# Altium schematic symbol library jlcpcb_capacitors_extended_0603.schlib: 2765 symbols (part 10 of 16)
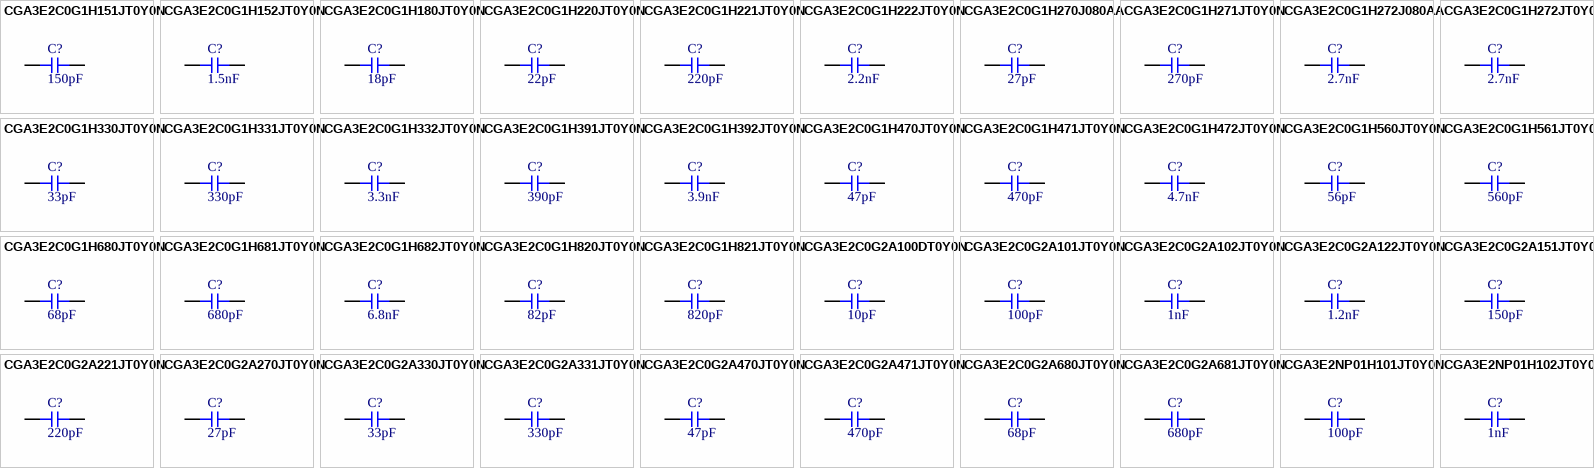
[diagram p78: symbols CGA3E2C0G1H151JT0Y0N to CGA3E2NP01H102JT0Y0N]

## CGA3E2C0G1H680JT0Y0N
designator C?  Capacitance: 68pF  (hidden comment: *)
Capacitor, Ceramic (MLCC), 68pF, ±5%, 50V, C0G, ±5%, SMD 0603; Manufacturer: TDK; Manufacturer Part Number: CGA3E2C0G1H680JT0Y0N
footprint CAP-0603 (0603 (1608M) Capacitor)
pins: 1, 2

## CGA3E2C0G1H681JT0Y0N
designator C?  Capacitance: 680pF  (hidden comment: *)
Capacitor, Ceramic (MLCC), 680pF, ±5%, 50V, C0G, ±5%, SMD 0603; Manufacturer: TDK; Manufacturer Part Number: CGA3E2C0G1H681JT0Y0N
footprint CAP-0603 (0603 (1608M) Capacitor)
pins: 1, 2

## CGA3E2C0G1H682JT0Y0N
designator C?  Capacitance: 6.8nF  (hidden comment: *)
Capacitor, Ceramic (MLCC), 6.8nF, ±5%, 50V, C0G, ±5%, SMD 0603; Manufacturer: TDK; Manufacturer Part Number: CGA3E2C0G1H682JT0Y0N
footprint CAP-0603 (0603 (1608M) Capacitor)
pins: 1, 2

## CGA3E2C0G1H820JT0Y0N
designator C?  Capacitance: 82pF  (hidden comment: *)
Capacitor, Ceramic (MLCC), 82pF, ±5%, 50V, C0G, ±5%, SMD 0603; Manufacturer: TDK; Manufacturer Part Number: CGA3E2C0G1H820JT0Y0N
footprint CAP-0603 (0603 (1608M) Capacitor)
pins: 1, 2

## CGA3E2C0G1H821JT0Y0N
designator C?  Capacitance: 820pF  (hidden comment: *)
Capacitor, Ceramic (MLCC), 820pF, ±5%, 50V, C0G, ±5%, SMD 0603; Manufacturer: TDK; Manufacturer Part Number: CGA3E2C0G1H821JT0Y0N
footprint CAP-0603 (0603 (1608M) Capacitor)
pins: 1, 2

## CGA3E2C0G2A100DT0Y0N
designator C?  Capacitance: 10pF  (hidden comment: *)
Capacitor, Ceramic (MLCC), 10pF, ±0.5pF, 100V, C0G, ±0.5pF, SMD 0603; Manufacturer: TDK; Manufacturer Part Number: CGA3E2C0G2A100DT0Y0N
footprint CAP-0603 (0603 (1608M) Capacitor)
pins: 1, 2

## CGA3E2C0G2A101JT0Y0N
designator C?  Capacitance: 100pF  (hidden comment: *)
Capacitor, Ceramic (MLCC), 100pF, ±5%, 100V, C0G, ±5%, SMD 0603; Manufacturer: TDK; Manufacturer Part Number: CGA3E2C0G2A101JT0Y0N
footprint CAP-0603 (0603 (1608M) Capacitor)
pins: 1, 2

## CGA3E2C0G2A102JT0Y0N
designator C?  Capacitance: 1nF  (hidden comment: *)
Capacitor, Ceramic (MLCC), 1nF, ±5%, 100V, C0G, ±5%, SMD 0603; Manufacturer: TDK; Manufacturer Part Number: CGA3E2C0G2A102JT0Y0N
footprint CAP-0603 (0603 (1608M) Capacitor)
pins: 1, 2

## CGA3E2C0G2A122JT0Y0N
designator C?  Capacitance: 1.2nF  (hidden comment: *)
Capacitor, Ceramic (MLCC), 1.2nF, ±5%, 100V, C0G, ±5%, SMD 0603; Manufacturer: TDK; Manufacturer Part Number: CGA3E2C0G2A122JT0Y0N
footprint CAP-0603 (0603 (1608M) Capacitor)
pins: 1, 2

## CGA3E2C0G2A151JT0Y0N
designator C?  Capacitance: 150pF  (hidden comment: *)
Capacitor, Ceramic (MLCC), 150pF, ±5%, 100V, C0G, ±5%, SMD 0603; Manufacturer: TDK; Manufacturer Part Number: CGA3E2C0G2A151JT0Y0N
footprint CAP-0603 (0603 (1608M) Capacitor)
pins: 1, 2

## CGA3E2C0G2A221JT0Y0N
designator C?  Capacitance: 220pF  (hidden comment: *)
Capacitor, Ceramic (MLCC), 220pF, ±5%, 100V, C0G, ±5%, SMD 0603; Manufacturer: TDK; Manufacturer Part Number: CGA3E2C0G2A221JT0Y0N
footprint CAP-0603 (0603 (1608M) Capacitor)
pins: 1, 2

## CGA3E2C0G2A270JT0Y0N
designator C?  Capacitance: 27pF  (hidden comment: *)
Capacitor, Ceramic (MLCC), 27pF, ±5%, 100V, C0G, ±5%, SMD 0603; Manufacturer: TDK; Manufacturer Part Number: CGA3E2C0G2A270JT0Y0N
footprint CAP-0603 (0603 (1608M) Capacitor)
pins: 1, 2

## CGA3E2C0G2A330JT0Y0N
designator C?  Capacitance: 33pF  (hidden comment: *)
Capacitor, Ceramic (MLCC), 33pF, ±5%, 100V, C0G, ±5%, SMD 0603; Manufacturer: TDK; Manufacturer Part Number: CGA3E2C0G2A330JT0Y0N
footprint CAP-0603 (0603 (1608M) Capacitor)
pins: 1, 2

## CGA3E2C0G2A331JT0Y0N
designator C?  Capacitance: 330pF  (hidden comment: *)
Capacitor, Ceramic (MLCC), 330pF, ±5%, 100V, C0G, ±5%, SMD 0603; Manufacturer: TDK; Manufacturer Part Number: CGA3E2C0G2A331JT0Y0N
footprint CAP-0603 (0603 (1608M) Capacitor)
pins: 1, 2

## CGA3E2C0G2A470JT0Y0N
designator C?  Capacitance: 47pF  (hidden comment: *)
Capacitor, Ceramic (MLCC), 47pF, ±5%, 100V, C0G, ±5%, SMD 0603; Manufacturer: TDK; Manufacturer Part Number: CGA3E2C0G2A470JT0Y0N
footprint CAP-0603 (0603 (1608M) Capacitor)
pins: 1, 2

## CGA3E2C0G2A471JT0Y0N
designator C?  Capacitance: 470pF  (hidden comment: *)
Capacitor, Ceramic (MLCC), 470pF, ±5%, 100V, C0G, ±5%, SMD 0603; Manufacturer: TDK; Manufacturer Part Number: CGA3E2C0G2A471JT0Y0N
footprint CAP-0603 (0603 (1608M) Capacitor)
pins: 1, 2

## CGA3E2C0G2A680JT0Y0N
designator C?  Capacitance: 68pF  (hidden comment: *)
Capacitor, Ceramic (MLCC), 68pF, ±5%, 100V, C0G, ±5%, SMD 0603; Manufacturer: TDK; Manufacturer Part Number: CGA3E2C0G2A680JT0Y0N
footprint CAP-0603 (0603 (1608M) Capacitor)
pins: 1, 2

## CGA3E2C0G2A681JT0Y0N
designator C?  Capacitance: 680pF  (hidden comment: *)
Capacitor, Ceramic (MLCC), 680pF, ±5%, 100V, C0G, ±5%, SMD 0603; Manufacturer: TDK; Manufacturer Part Number: CGA3E2C0G2A681JT0Y0N
footprint CAP-0603 (0603 (1608M) Capacitor)
pins: 1, 2

## CGA3E2NP01H101JT0Y0N
designator C?  Capacitance: 100pF  (hidden comment: *)
Capacitor, Ceramic (MLCC), 100pF, ±5%, 50V, NP0, ±5%, SMD 0603; Manufacturer: TDK; Manufacturer Part Number: CGA3E2NP01H101JT0Y0N
footprint CAP-0603 (0603 (1608M) Capacitor)
pins: 1, 2

## CGA3E2NP01H102JT0Y0N
designator C?  Capacitance: 1nF  (hidden comment: *)
Capacitor, Ceramic (MLCC), 1nF, ±5%, 50V, NP0, ±5%, SMD 0603; Manufacturer: TDK; Manufacturer Part Number: CGA3E2NP01H102JT0Y0N
footprint CAP-0603 (0603 (1608M) Capacitor)
pins: 1, 2

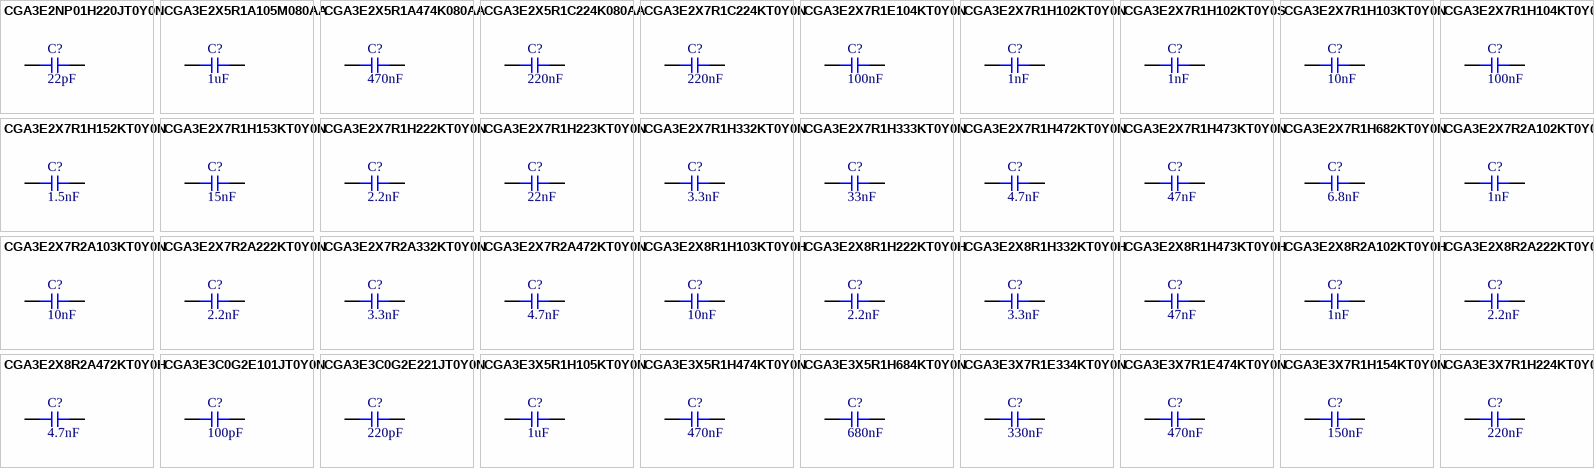
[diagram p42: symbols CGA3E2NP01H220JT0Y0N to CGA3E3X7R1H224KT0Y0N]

## CGA3E2NP01H220JT0Y0N
designator C?  Capacitance: 22pF  (hidden comment: *)
Capacitor, Ceramic (MLCC), 22pF, ±5%, 50V, NP0, ±5%, SMD 0603; Manufacturer: TDK; Manufacturer Part Number: CGA3E2NP01H220JT0Y0N
footprint CAP-0603 (0603 (1608M) Capacitor)
pins: 1, 2

## CGA3E2X5R1A105M080AA
designator C?  Capacitance: 1uF  (hidden comment: *)
Capacitor, Ceramic (MLCC), 1uF, ±20%, 10V, X5R, ±20%, SMD 0603; Manufacturer: TDK; Manufacturer Part Number: CGA3E2X5R1A105M080AA
footprint CAP-0603 (0603 (1608M) Capacitor)
pins: 1, 2

## CGA3E2X5R1A474K080AA
designator C?  Capacitance: 470nF  (hidden comment: *)
Capacitor, Ceramic (MLCC), 470nF, ±10%, 10V, X5R, ±10%, SMD 0603; Manufacturer: TDK; Manufacturer Part Number: CGA3E2X5R1A474K080AA
footprint CAP-0603 (0603 (1608M) Capacitor)
pins: 1, 2

## CGA3E2X5R1C224K080AA
designator C?  Capacitance: 220nF  (hidden comment: *)
Capacitor, Ceramic (MLCC), 220nF, ±10%, 16V, X5R, ±10%, SMD 0603; Manufacturer: TDK; Manufacturer Part Number: CGA3E2X5R1C224K080AA
footprint CAP-0603 (0603 (1608M) Capacitor)
pins: 1, 2

## CGA3E2X7R1C224KT0Y0N
designator C?  Capacitance: 220nF  (hidden comment: *)
Capacitor, Ceramic (MLCC), 220nF, ±10%, 16V, X7R, ±10%, SMD 0603; Manufacturer: TDK; Manufacturer Part Number: CGA3E2X7R1C224KT0Y0N
footprint CAP-0603 (0603 (1608M) Capacitor)
pins: 1, 2

## CGA3E2X7R1E104KT0Y0N
designator C?  Capacitance: 100nF  (hidden comment: *)
Capacitor, Ceramic (MLCC), 100nF, ±10%, 25V, X7R, ±10%, SMD 0603; Manufacturer: TDK; Manufacturer Part Number: CGA3E2X7R1E104KT0Y0N
footprint CAP-0603 (0603 (1608M) Capacitor)
pins: 1, 2

## CGA3E2X7R1H102KT0Y0N
designator C?  Capacitance: 1nF  (hidden comment: *)
Capacitor, Ceramic (MLCC), 1nF, ±10%, 50V, X7R, ±10%, SMD 0603; Manufacturer: TDK; Manufacturer Part Number: CGA3E2X7R1H102KT0Y0N
footprint CAP-0603 (0603 (1608M) Capacitor)
pins: 1, 2

## CGA3E2X7R1H102KT0Y0S
designator C?  Capacitance: 1nF  (hidden comment: *)
Capacitor, Ceramic (MLCC), 1nF, ±10%, 50V, X7R, ±10%, SMD 0603; Manufacturer: TDK; Manufacturer Part Number: CGA3E2X7R1H102KT0Y0S
footprint CAP-0603 (0603 (1608M) Capacitor)
pins: 1, 2

## CGA3E2X7R1H103KT0Y0N
designator C?  Capacitance: 10nF  (hidden comment: *)
Capacitor, Ceramic (MLCC), 10nF, ±10%, 50V, X7R, ±10%, SMD 0603; Manufacturer: TDK; Manufacturer Part Number: CGA3E2X7R1H103KT0Y0N
footprint CAP-0603 (0603 (1608M) Capacitor)
pins: 1, 2

## CGA3E2X7R1H104KT0Y0N
designator C?  Capacitance: 100nF  (hidden comment: *)
Capacitor, Ceramic (MLCC), 100nF, ±10%, 50V, X7R, ±10%, SMD 0603; Manufacturer: TDK; Manufacturer Part Number: CGA3E2X7R1H104KT0Y0N
footprint CAP-0603 (0603 (1608M) Capacitor)
pins: 1, 2

## CGA3E2X7R1H152KT0Y0N
designator C?  Capacitance: 1.5nF  (hidden comment: *)
Capacitor, Ceramic (MLCC), 1.5nF, ±10%, 50V, X7R, ±10%, SMD 0603; Manufacturer: TDK; Manufacturer Part Number: CGA3E2X7R1H152KT0Y0N
footprint CAP-0603 (0603 (1608M) Capacitor)
pins: 1, 2

## CGA3E2X7R1H153KT0Y0N
designator C?  Capacitance: 15nF  (hidden comment: *)
Capacitor, Ceramic (MLCC), 15nF, ±10%, 50V, X7R, ±10%, SMD 0603; Manufacturer: TDK; Manufacturer Part Number: CGA3E2X7R1H153KT0Y0N
footprint CAP-0603 (0603 (1608M) Capacitor)
pins: 1, 2

## CGA3E2X7R1H222KT0Y0N
designator C?  Capacitance: 2.2nF  (hidden comment: *)
Capacitor, Ceramic (MLCC), 2.2nF, ±10%, 50V, X7R, ±10%, SMD 0603; Manufacturer: TDK; Manufacturer Part Number: CGA3E2X7R1H222KT0Y0N
footprint CAP-0603 (0603 (1608M) Capacitor)
pins: 1, 2

## CGA3E2X7R1H223KT0Y0N
designator C?  Capacitance: 22nF  (hidden comment: *)
Capacitor, Ceramic (MLCC), 22nF, ±10%, 50V, X7R, ±10%, SMD 0603; Manufacturer: TDK; Manufacturer Part Number: CGA3E2X7R1H223KT0Y0N
footprint CAP-0603 (0603 (1608M) Capacitor)
pins: 1, 2

## CGA3E2X7R1H332KT0Y0N
designator C?  Capacitance: 3.3nF  (hidden comment: *)
Capacitor, Ceramic (MLCC), 3.3nF, ±10%, 50V, X7R, ±10%, SMD 0603; Manufacturer: TDK; Manufacturer Part Number: CGA3E2X7R1H332KT0Y0N
footprint CAP-0603 (0603 (1608M) Capacitor)
pins: 1, 2

## CGA3E2X7R1H333KT0Y0N
designator C?  Capacitance: 33nF  (hidden comment: *)
Capacitor, Ceramic (MLCC), 33nF, ±10%, 50V, X7R, ±10%, SMD 0603; Manufacturer: TDK; Manufacturer Part Number: CGA3E2X7R1H333KT0Y0N
footprint CAP-0603 (0603 (1608M) Capacitor)
pins: 1, 2

## CGA3E2X7R1H472KT0Y0N
designator C?  Capacitance: 4.7nF  (hidden comment: *)
Capacitor, Ceramic (MLCC), 4.7nF, ±10%, 50V, X7R, ±10%, SMD 0603; Manufacturer: TDK; Manufacturer Part Number: CGA3E2X7R1H472KT0Y0N
footprint CAP-0603 (0603 (1608M) Capacitor)
pins: 1, 2

## CGA3E2X7R1H473KT0Y0N
designator C?  Capacitance: 47nF  (hidden comment: *)
Capacitor, Ceramic (MLCC), 47nF, ±10%, 50V, X7R, ±10%, SMD 0603; Manufacturer: TDK; Manufacturer Part Number: CGA3E2X7R1H473KT0Y0N
footprint CAP-0603 (0603 (1608M) Capacitor)
pins: 1, 2

## CGA3E2X7R1H682KT0Y0N
designator C?  Capacitance: 6.8nF  (hidden comment: *)
Capacitor, Ceramic (MLCC), 6.8nF, ±10%, 50V, X7R, ±10%, SMD 0603; Manufacturer: TDK; Manufacturer Part Number: CGA3E2X7R1H682KT0Y0N
footprint CAP-0603 (0603 (1608M) Capacitor)
pins: 1, 2

## CGA3E2X7R2A102KT0Y0N
designator C?  Capacitance: 1nF  (hidden comment: *)
Capacitor, Ceramic (MLCC), 1nF, ±10%, 100V, X7R, ±10%, SMD 0603; Manufacturer: TDK; Manufacturer Part Number: CGA3E2X7R2A102KT0Y0N
footprint CAP-0603 (0603 (1608M) Capacitor)
pins: 1, 2

## CGA3E2X7R2A103KT0Y0N
designator C?  Capacitance: 10nF  (hidden comment: *)
Capacitor, Ceramic (MLCC), 10nF, ±10%, 100V, X7R, ±10%, SMD 0603; Manufacturer: TDK; Manufacturer Part Number: CGA3E2X7R2A103KT0Y0N
footprint CAP-0603 (0603 (1608M) Capacitor)
pins: 1, 2

## CGA3E2X7R2A222KT0Y0N
designator C?  Capacitance: 2.2nF  (hidden comment: *)
Capacitor, Ceramic (MLCC), 2.2nF, ±10%, 100V, X7R, ±10%, SMD 0603; Manufacturer: TDK; Manufacturer Part Number: CGA3E2X7R2A222KT0Y0N
footprint CAP-0603 (0603 (1608M) Capacitor)
pins: 1, 2

## CGA3E2X7R2A332KT0Y0N
designator C?  Capacitance: 3.3nF  (hidden comment: *)
Capacitor, Ceramic (MLCC), 3.3nF, ±10%, 100V, X7R, ±10%, SMD 0603; Manufacturer: TDK; Manufacturer Part Number: CGA3E2X7R2A332KT0Y0N
footprint CAP-0603 (0603 (1608M) Capacitor)
pins: 1, 2

## CGA3E2X7R2A472KT0Y0N
designator C?  Capacitance: 4.7nF  (hidden comment: *)
Capacitor, Ceramic (MLCC), 4.7nF, ±10%, 100V, X7R, ±10%, SMD 0603; Manufacturer: TDK; Manufacturer Part Number: CGA3E2X7R2A472KT0Y0N
footprint CAP-0603 (0603 (1608M) Capacitor)
pins: 1, 2

## CGA3E2X8R1H103KT0Y0H
designator C?  Capacitance: 10nF  (hidden comment: *)
Capacitor, Ceramic (MLCC), 10nF, ±10%, 50V, X8R, ±10%, SMD 0603; Manufacturer: TDK; Manufacturer Part Number: CGA3E2X8R1H103KT0Y0H
footprint CAP-0603 (0603 (1608M) Capacitor)
pins: 1, 2

## CGA3E2X8R1H222KT0Y0H
designator C?  Capacitance: 2.2nF  (hidden comment: *)
Capacitor, Ceramic (MLCC), 2.2nF, ±10%, 50V, X8R, ±10%, SMD 0603; Manufacturer: TDK; Manufacturer Part Number: CGA3E2X8R1H222KT0Y0H
footprint CAP-0603 (0603 (1608M) Capacitor)
pins: 1, 2

## CGA3E2X8R1H332KT0Y0H
designator C?  Capacitance: 3.3nF  (hidden comment: *)
Capacitor, Ceramic (MLCC), 3.3nF, ±10%, 50V, X8R, ±10%, SMD 0603; Manufacturer: TDK; Manufacturer Part Number: CGA3E2X8R1H332KT0Y0H
footprint CAP-0603 (0603 (1608M) Capacitor)
pins: 1, 2

## CGA3E2X8R1H473KT0Y0H
designator C?  Capacitance: 47nF  (hidden comment: *)
Capacitor, Ceramic (MLCC), 47nF, ±10%, 50V, X8R, ±10%, SMD 0603; Manufacturer: TDK; Manufacturer Part Number: CGA3E2X8R1H473KT0Y0H
footprint CAP-0603 (0603 (1608M) Capacitor)
pins: 1, 2

## CGA3E2X8R2A102KT0Y0H
designator C?  Capacitance: 1nF  (hidden comment: *)
Capacitor, Ceramic (MLCC), 1nF, ±10%, 100V, X8R, ±10%, SMD 0603; Manufacturer: TDK; Manufacturer Part Number: CGA3E2X8R2A102KT0Y0H
footprint CAP-0603 (0603 (1608M) Capacitor)
pins: 1, 2

## CGA3E2X8R2A222KT0Y0H
designator C?  Capacitance: 2.2nF  (hidden comment: *)
Capacitor, Ceramic (MLCC), 2.2nF, ±10%, 100V, X8R, ±10%, SMD 0603; Manufacturer: TDK; Manufacturer Part Number: CGA3E2X8R2A222KT0Y0H
footprint CAP-0603 (0603 (1608M) Capacitor)
pins: 1, 2

## CGA3E2X8R2A472KT0Y0H
designator C?  Capacitance: 4.7nF  (hidden comment: *)
Capacitor, Ceramic (MLCC), 4.7nF, ±10%, 100V, X8R, ±10%, SMD 0603; Manufacturer: TDK; Manufacturer Part Number: CGA3E2X8R2A472KT0Y0H
footprint CAP-0603 (0603 (1608M) Capacitor)
pins: 1, 2

## CGA3E3C0G2E101JT0Y0N
designator C?  Capacitance: 100pF  (hidden comment: *)
Capacitor, Ceramic (MLCC), 100pF, ±5%, 250V, C0G, ±5%, SMD 0603; Manufacturer: TDK; Manufacturer Part Number: CGA3E3C0G2E101JT0Y0N
footprint CAP-0603 (0603 (1608M) Capacitor)
pins: 1, 2

## CGA3E3C0G2E221JT0Y0N
designator C?  Capacitance: 220pF  (hidden comment: *)
Capacitor, Ceramic (MLCC), 220pF, ±5%, 250V, C0G, ±5%, SMD 0603; Manufacturer: TDK; Manufacturer Part Number: CGA3E3C0G2E221JT0Y0N
footprint CAP-0603 (0603 (1608M) Capacitor)
pins: 1, 2

## CGA3E3X5R1H105KT0Y0N
designator C?  Capacitance: 1uF  (hidden comment: *)
Capacitor, Ceramic (MLCC), 1uF, ±10%, 50V, X5R, ±10%, SMD 0603; Manufacturer: TDK; Manufacturer Part Number: CGA3E3X5R1H105KT0Y0N
footprint CAP-0603 (0603 (1608M) Capacitor)
pins: 1, 2

## CGA3E3X5R1H474KT0Y0N
designator C?  Capacitance: 470nF  (hidden comment: *)
Capacitor, Ceramic (MLCC), 470nF, ±10%, 50V, X5R, ±10%, SMD 0603; Manufacturer: TDK; Manufacturer Part Number: CGA3E3X5R1H474KT0Y0N
footprint CAP-0603 (0603 (1608M) Capacitor)
pins: 1, 2

## CGA3E3X5R1H684KT0Y0N
designator C?  Capacitance: 680nF  (hidden comment: *)
Capacitor, Ceramic (MLCC), 680nF, ±10%, 50V, X5R, ±10%, SMD 0603; Manufacturer: TDK; Manufacturer Part Number: CGA3E3X5R1H684KT0Y0N
footprint CAP-0603 (0603 (1608M) Capacitor)
pins: 1, 2

## CGA3E3X7R1E334KT0Y0N
designator C?  Capacitance: 330nF  (hidden comment: *)
Capacitor, Ceramic (MLCC), 330nF, ±10%, 25V, X7R, ±10%, SMD 0603; Manufacturer: TDK; Manufacturer Part Number: CGA3E3X7R1E334KT0Y0N
footprint CAP-0603 (0603 (1608M) Capacitor)
pins: 1, 2

## CGA3E3X7R1E474KT0Y0N
designator C?  Capacitance: 470nF  (hidden comment: *)
Capacitor, Ceramic (MLCC), 470nF, ±10%, 25V, X7R, ±10%, SMD 0603; Manufacturer: TDK; Manufacturer Part Number: CGA3E3X7R1E474KT0Y0N
footprint CAP-0603 (0603 (1608M) Capacitor)
pins: 1, 2

## CGA3E3X7R1H154KT0Y0N
designator C?  Capacitance: 150nF  (hidden comment: *)
Capacitor, Ceramic (MLCC), 150nF, ±10%, 50V, X7R, ±10%, SMD 0603; Manufacturer: TDK; Manufacturer Part Number: CGA3E3X7R1H154KT0Y0N
footprint CAP-0603 (0603 (1608M) Capacitor)
pins: 1, 2

## CGA3E3X7R1H224KT0Y0N
designator C?  Capacitance: 220nF  (hidden comment: *)
Capacitor, Ceramic (MLCC), 220nF, ±10%, 50V, X7R, ±10%, SMD 0603; Manufacturer: TDK; Manufacturer Part Number: CGA3E3X7R1H224KT0Y0N
footprint CAP-0603 (0603 (1608M) Capacitor)
pins: 1, 2

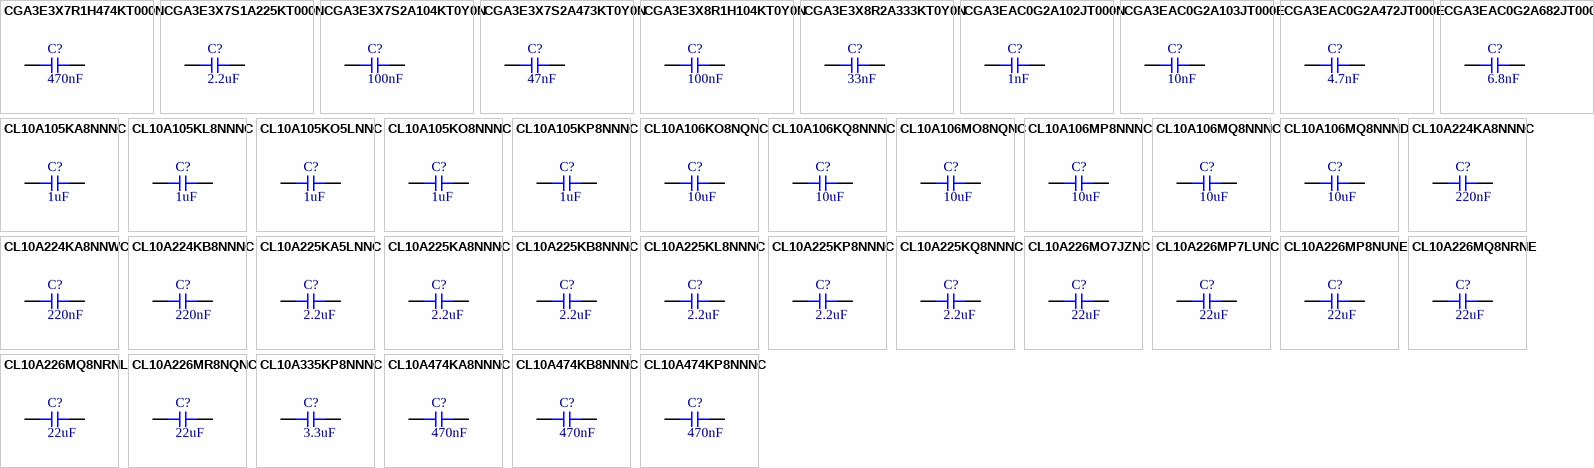
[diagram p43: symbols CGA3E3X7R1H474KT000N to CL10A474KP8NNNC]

## CGA3E3X7R1H474KT000N
designator C?  Capacitance: 470nF  (hidden comment: *)
Capacitor, Ceramic (MLCC), 470nF, ±10%, 50V, X7R, ±10%, SMD 0603; Manufacturer: TDK; Manufacturer Part Number: CGA3E3X7R1H474KT000N
footprint CAP-0603 (0603 (1608M) Capacitor)
pins: 1, 2

## CGA3E3X7S1A225KT000N
designator C?  Capacitance: 2.2uF  (hidden comment: *)
Capacitor, Ceramic (MLCC), 2.2uF, ±10%, 10V, X7S, ±10%, SMD 0603; Manufacturer: TDK; Manufacturer Part Number: CGA3E3X7S1A225KT000N
footprint CAP-0603 (0603 (1608M) Capacitor)
pins: 1, 2

## CGA3E3X7S2A104KT0Y0N
designator C?  Capacitance: 100nF  (hidden comment: *)
Capacitor, Ceramic (MLCC), 100nF, ±10%, 100V, X7S, ±10%, SMD 0603; Manufacturer: TDK; Manufacturer Part Number: CGA3E3X7S2A104KT0Y0N
footprint CAP-0603 (0603 (1608M) Capacitor)
pins: 1, 2

## CGA3E3X7S2A473KT0Y0N
designator C?  Capacitance: 47nF  (hidden comment: *)
Capacitor, Ceramic (MLCC), 47nF, ±10%, 100V, X7S, ±10%, SMD 0603; Manufacturer: TDK; Manufacturer Part Number: CGA3E3X7S2A473KT0Y0N
footprint CAP-0603 (0603 (1608M) Capacitor)
pins: 1, 2

## CGA3E3X8R1H104KT0Y0N
designator C?  Capacitance: 100nF  (hidden comment: *)
Capacitor, Ceramic (MLCC), 100nF, ±10%, 50V, X8R, ±10%, SMD 0603; Manufacturer: TDK; Manufacturer Part Number: CGA3E3X8R1H104KT0Y0N
footprint CAP-0603 (0603 (1608M) Capacitor)
pins: 1, 2

## CGA3E3X8R2A333KT0Y0N
designator C?  Capacitance: 33nF  (hidden comment: *)
Capacitor, Ceramic (MLCC), 33nF, ±10%, 100V, X8R, ±10%, SMD 0603; Manufacturer: TDK; Manufacturer Part Number: CGA3E3X8R2A333KT0Y0N
footprint CAP-0603 (0603 (1608M) Capacitor)
pins: 1, 2

## CGA3EAC0G2A102JT000N
designator C?  Capacitance: 1nF  (hidden comment: *)
Capacitor, Ceramic (MLCC), 1nF, ±5%, 100V, C0G, ±5%, SMD 0603; Manufacturer: TDK; Manufacturer Part Number: CGA3EAC0G2A102JT000N
footprint CAP-0603 (0603 (1608M) Capacitor)
pins: 1, 2

## CGA3EAC0G2A103JT000E
designator C?  Capacitance: 10nF  (hidden comment: *)
Capacitor, Ceramic (MLCC), 10nF, ±5%, 100V, C0G, ±5%, SMD 0603; Manufacturer: TDK; Manufacturer Part Number: CGA3EAC0G2A103JT000E
footprint CAP-0603 (0603 (1608M) Capacitor)
pins: 1, 2

## CGA3EAC0G2A472JT000E
designator C?  Capacitance: 4.7nF  (hidden comment: *)
Capacitor, Ceramic (MLCC), 4.7nF, ±5%, 100V, C0G, ±5%, SMD 0603; Manufacturer: TDK; Manufacturer Part Number: CGA3EAC0G2A472JT000E
footprint CAP-0603 (0603 (1608M) Capacitor)
pins: 1, 2

## CGA3EAC0G2A682JT000E
designator C?  Capacitance: 6.8nF  (hidden comment: *)
Capacitor, Ceramic (MLCC), 6.8nF, ±5%, 100V, C0G, ±5%, SMD 0603; Manufacturer: TDK; Manufacturer Part Number: CGA3EAC0G2A682JT000E
footprint CAP-0603 (0603 (1608M) Capacitor)
pins: 1, 2

## CL10A105KA8NNNC
designator C?  Capacitance: 1uF  (hidden comment: *)
Capacitor, Ceramic (MLCC), 1uF, ±10%, 25V, X5R, ±10%, SMD 0603; Manufacturer: Samsung Electro-Mechanics; Manufacturer Part Number: CL10A105KA8NNNC
footprint CAP-0603 (0603 (1608M) Capacitor)
pins: 1, 2

## CL10A105KL8NNNC
designator C?  Capacitance: 1uF  (hidden comment: *)
Capacitor, Ceramic (MLCC), 1uF, ±10%, 35V, ±10%, SMD 0603; Manufacturer: Samsung Electro-Mechanics; Manufacturer Part Number: CL10A105KL8NNNC
footprint CAP-0603 (0603 (1608M) Capacitor)
pins: 1, 2

## CL10A105KO5LNNC
designator C?  Capacitance: 1uF  (hidden comment: *)
Capacitor, Ceramic (MLCC), 1uF, ±10%, 16V, X5R, ±10%, SMD 0603; Manufacturer: Samsung Electro-Mechanics; Manufacturer Part Number: CL10A105KO5LNNC
footprint CAP-0603 (0603 (1608M) Capacitor)
pins: 1, 2

## CL10A105KO8NNNC
designator C?  Capacitance: 1uF  (hidden comment: *)
Capacitor, Ceramic (MLCC), 1uF, ±10%, 16V, X5R, ±10%, SMD 0603; Manufacturer: Samsung Electro-Mechanics; Manufacturer Part Number: CL10A105KO8NNNC
footprint CAP-0603 (0603 (1608M) Capacitor)
pins: 1, 2

## CL10A105KP8NNNC
designator C?  Capacitance: 1uF  (hidden comment: *)
Capacitor, Ceramic (MLCC), 1uF, ±10%, 10V, X5R, ±10%, SMD 0603; Manufacturer: Samsung Electro-Mechanics; Manufacturer Part Number: CL10A105KP8NNNC
footprint CAP-0603 (0603 (1608M) Capacitor)
pins: 1, 2

## CL10A106KO8NQNC
designator C?  Capacitance: 10uF  (hidden comment: *)
Capacitor, Ceramic (MLCC), 10uF, ±10%, 16V, ±10%, SMD 0603; Manufacturer: Samsung Electro-Mechanics; Manufacturer Part Number: CL10A106KO8NQNC
footprint CAP-0603 (0603 (1608M) Capacitor)
pins: 1, 2

## CL10A106KQ8NNNC
designator C?  Capacitance: 10uF  (hidden comment: *)
Capacitor, Ceramic (MLCC), 10uF, ±10%, 6.3V, X5R, ±10%, SMD 0603; Manufacturer: Samsung Electro-Mechanics; Manufacturer Part Number: CL10A106KQ8NNNC
footprint CAP-0603 (0603 (1608M) Capacitor)
pins: 1, 2

## CL10A106MO8NQNC
designator C?  Capacitance: 10uF  (hidden comment: *)
Capacitor, Ceramic (MLCC), 10uF, ±20%, 16V, X5R, ±20%, SMD 0603; Manufacturer: Samsung Electro-Mechanics; Manufacturer Part Number: CL10A106MO8NQNC
footprint CAP-0603 (0603 (1608M) Capacitor)
pins: 1, 2

## CL10A106MP8NNNC
designator C?  Capacitance: 10uF  (hidden comment: *)
Capacitor, Ceramic (MLCC), 10uF, ±20%, 10V, X5R, ±20%, SMD 0603; Manufacturer: Samsung Electro-Mechanics; Manufacturer Part Number: CL10A106MP8NNNC
footprint CAP-0603 (0603 (1608M) Capacitor)
pins: 1, 2

## CL10A106MQ8NNNC
designator C?  Capacitance: 10uF  (hidden comment: *)
Capacitor, Ceramic (MLCC), 10uF, ±20%, 6.3V, X5R, ±20%, SMD 0603; Manufacturer: Samsung Electro-Mechanics; Manufacturer Part Number: CL10A106MQ8NNNC
footprint CAP-0603 (0603 (1608M) Capacitor)
pins: 1, 2

## CL10A106MQ8NNND
designator C?  Capacitance: 10uF  (hidden comment: *)
Capacitor, Ceramic (MLCC), 10uF, ±20%, 6.3V, X5R, ±20%, SMD 0603; Manufacturer: Samsung Electro-Mechanics; Manufacturer Part Number: CL10A106MQ8NNND
footprint CAP-0603 (0603 (1608M) Capacitor)
pins: 1, 2

## CL10A224KA8NNNC
designator C?  Capacitance: 220nF  (hidden comment: *)
Capacitor, Ceramic (MLCC), 220nF, ±10%, 25V, X5R, ±10%, SMD 0603; Manufacturer: Samsung Electro-Mechanics; Manufacturer Part Number: CL10A224KA8NNNC
footprint CAP-0603 (0603 (1608M) Capacitor)
pins: 1, 2

## CL10A224KA8NNWC
designator C?  Capacitance: 220nF  (hidden comment: *)
Capacitor, Ceramic (MLCC), 220nF, ±10%, 25V, X5R, ±10%, SMD 0603; Manufacturer: Samsung Electro-Mechanics; Manufacturer Part Number: CL10A224KA8NNWC
footprint CAP-0603 (0603 (1608M) Capacitor)
pins: 1, 2

## CL10A224KB8NNNC
designator C?  Capacitance: 220nF  (hidden comment: *)
Capacitor, Ceramic (MLCC), 220nF, ±10%, 50V, X5R, ±10%, SMD 0603; Manufacturer: Samsung Electro-Mechanics; Manufacturer Part Number: CL10A224KB8NNNC
footprint CAP-0603 (0603 (1608M) Capacitor)
pins: 1, 2

## CL10A225KA5LNNC
designator C?  Capacitance: 2.2uF  (hidden comment: *)
Capacitor, Ceramic (MLCC), 2.2uF, ±10%, 25V, X5R, ±10%, SMD 0603; Manufacturer: Samsung Electro-Mechanics; Manufacturer Part Number: CL10A225KA5LNNC
footprint CAP-0603 (0603 (1608M) Capacitor)
pins: 1, 2

## CL10A225KA8NNNC
designator C?  Capacitance: 2.2uF  (hidden comment: *)
Capacitor, Ceramic (MLCC), 2.2uF, ±10%, 25V, X5R, ±10%, SMD 0603; Manufacturer: Samsung Electro-Mechanics; Manufacturer Part Number: CL10A225KA8NNNC
footprint CAP-0603 (0603 (1608M) Capacitor)
pins: 1, 2

## CL10A225KB8NNNC
designator C?  Capacitance: 2.2uF  (hidden comment: *)
Capacitor, Ceramic (MLCC), 2.2uF, ±10%, 50V, ±10%, SMD 0603; Manufacturer: Samsung Electro-Mechanics; Manufacturer Part Number: CL10A225KB8NNNC
footprint CAP-0603 (0603 (1608M) Capacitor)
pins: 1, 2

## CL10A225KL8NNNC
designator C?  Capacitance: 2.2uF  (hidden comment: *)
Capacitor, Ceramic (MLCC), 2.2uF, ±10%, 35V, X5R, ±10%, SMD 0603; Manufacturer: Samsung Electro-Mechanics; Manufacturer Part Number: CL10A225KL8NNNC
footprint CAP-0603 (0603 (1608M) Capacitor)
pins: 1, 2

## CL10A225KP8NNNC
designator C?  Capacitance: 2.2uF  (hidden comment: *)
Capacitor, Ceramic (MLCC), 2.2uF, ±10%, 10V, X5R, ±10%, SMD 0603; Manufacturer: Samsung Electro-Mechanics; Manufacturer Part Number: CL10A225KP8NNNC
footprint CAP-0603 (0603 (1608M) Capacitor)
pins: 1, 2

## CL10A225KQ8NNNC
designator C?  Capacitance: 2.2uF  (hidden comment: *)
Capacitor, Ceramic (MLCC), 2.2uF, ±10%, 6.3V, X5R, ±10%, SMD 0603; Manufacturer: Samsung Electro-Mechanics; Manufacturer Part Number: CL10A225KQ8NNNC
footprint CAP-0603 (0603 (1608M) Capacitor)
pins: 1, 2

## CL10A226MO7JZNC
designator C?  Capacitance: 22uF  (hidden comment: *)
Capacitor, Ceramic (MLCC), 22uF, ±20%, 16V, ±20%, SMD 0603; Manufacturer: Samsung Electro-Mechanics; Manufacturer Part Number: CL10A226MO7JZNC
footprint CAP-0603 (0603 (1608M) Capacitor)
pins: 1, 2

## CL10A226MP7LUNC
designator C?  Capacitance: 22uF  (hidden comment: *)
Capacitor, Ceramic (MLCC), 22uF, ±20%, 10V, ±20%, SMD 0603; Manufacturer: Samsung Electro-Mechanics; Manufacturer Part Number: CL10A226MP7LUNC
footprint CAP-0603 (0603 (1608M) Capacitor)
pins: 1, 2

## CL10A226MP8NUNE
designator C?  Capacitance: 22uF  (hidden comment: *)
Capacitor, Ceramic (MLCC), 22uF, ±20%, 10V, X5R, ±20%, SMD 0603; Manufacturer: Samsung Electro-Mechanics; Manufacturer Part Number: CL10A226MP8NUNE
footprint CAP-0603 (0603 (1608M) Capacitor)
pins: 1, 2

## CL10A226MQ8NRNE
designator C?  Capacitance: 22uF  (hidden comment: *)
Capacitor, Ceramic (MLCC), 22uF, ±20%, 6.3V, X5R, ±20%, SMD 0603; Manufacturer: Samsung Electro-Mechanics; Manufacturer Part Number: CL10A226MQ8NRNE
footprint CAP-0603 (0603 (1608M) Capacitor)
pins: 1, 2

## CL10A226MQ8NRNL
designator C?  Capacitance: 22uF  (hidden comment: *)
Capacitor, Ceramic (MLCC), 22uF, ±20%, 6.3V, X5R, ±20%, SMD 0603; Manufacturer: Samsung Electro-Mechanics; Manufacturer Part Number: CL10A226MQ8NRNL
footprint CAP-0603 (0603 (1608M) Capacitor)
pins: 1, 2

## CL10A226MR8NQNC
designator C?  Capacitance: 22uF  (hidden comment: *)
Capacitor, Ceramic (MLCC), 22uF, ±20%, 4V, X5R, ±20%, SMD 0603; Manufacturer: Samsung Electro-Mechanics; Manufacturer Part Number: CL10A226MR8NQNC
footprint CAP-0603 (0603 (1608M) Capacitor)
pins: 1, 2

## CL10A335KP8NNNC
designator C?  Capacitance: 3.3uF  (hidden comment: *)
Capacitor, Ceramic (MLCC), 3.3uF, ±10%, 10V, X5R, ±10%, SMD 0603; Manufacturer: Samsung Electro-Mechanics; Manufacturer Part Number: CL10A335KP8NNNC
footprint CAP-0603 (0603 (1608M) Capacitor)
pins: 1, 2

## CL10A474KA8NNNC
designator C?  Capacitance: 470nF  (hidden comment: *)
Capacitor, Ceramic (MLCC), 470nF, ±10%, 25V, X5R, ±10%, SMD 0603; Manufacturer: Samsung Electro-Mechanics; Manufacturer Part Number: CL10A474KA8NNNC
footprint CAP-0603 (0603 (1608M) Capacitor)
pins: 1, 2

## CL10A474KB8NNNC
designator C?  Capacitance: 470nF  (hidden comment: *)
Capacitor, Ceramic (MLCC), 470nF, ±10%, 50V, X5R, ±10%, SMD 0603; Manufacturer: Samsung Electro-Mechanics; Manufacturer Part Number: CL10A474KB8NNNC
footprint CAP-0603 (0603 (1608M) Capacitor)
pins: 1, 2

## CL10A474KP8NNNC
designator C?  Capacitance: 470nF  (hidden comment: *)
Capacitor, Ceramic (MLCC), 470nF, ±10%, 10V, X5R, ±10%, SMD 0603; Manufacturer: Samsung Electro-Mechanics; Manufacturer Part Number: CL10A474KP8NNNC
footprint CAP-0603 (0603 (1608M) Capacitor)
pins: 1, 2

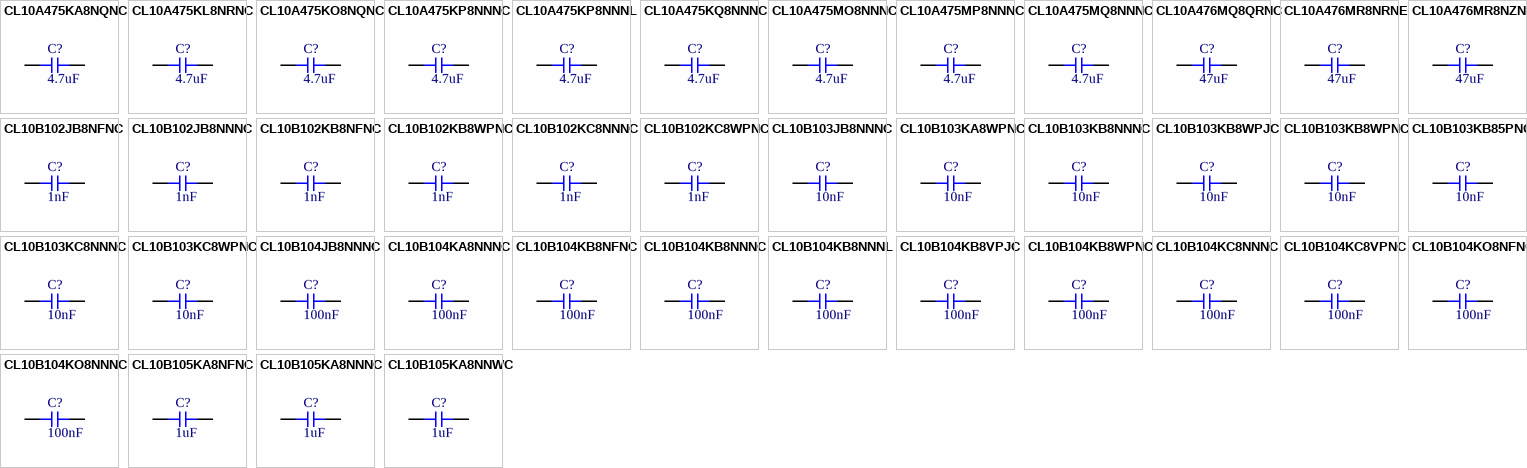
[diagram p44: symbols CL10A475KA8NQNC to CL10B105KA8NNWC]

## CL10A475KA8NQNC
designator C?  Capacitance: 4.7uF  (hidden comment: *)
Capacitor, Ceramic (MLCC), 4.7uF, ±10%, 25V, X5R, ±10%, SMD 0603; Manufacturer: Samsung Electro-Mechanics; Manufacturer Part Number: CL10A475KA8NQNC
footprint CAP-0603 (0603 (1608M) Capacitor)
pins: 1, 2

## CL10A475KL8NRNC
designator C?  Capacitance: 4.7uF  (hidden comment: *)
Capacitor, Ceramic (MLCC), 4.7uF, ±10%, 35V, X5R, ±10%, SMD 0603; Manufacturer: Samsung Electro-Mechanics; Manufacturer Part Number: CL10A475KL8NRNC
footprint CAP-0603 (0603 (1608M) Capacitor)
pins: 1, 2

## CL10A475KO8NQNC
designator C?  Capacitance: 4.7uF  (hidden comment: *)
Capacitor, Ceramic (MLCC), 4.7uF, ±10%, 16V, X5R, ±10%, SMD 0603; Manufacturer: Samsung Electro-Mechanics; Manufacturer Part Number: CL10A475KO8NQNC
footprint CAP-0603 (0603 (1608M) Capacitor)
pins: 1, 2

## CL10A475KP8NNNC
designator C?  Capacitance: 4.7uF  (hidden comment: *)
Capacitor, Ceramic (MLCC), 4.7uF, ±10%, 10V, X5R, ±10%, SMD 0603; Manufacturer: Samsung Electro-Mechanics; Manufacturer Part Number: CL10A475KP8NNNC
footprint CAP-0603 (0603 (1608M) Capacitor)
pins: 1, 2

## CL10A475KP8NNNL
designator C?  Capacitance: 4.7uF  (hidden comment: *)
Capacitor, Ceramic (MLCC), 4.7uF, ±10%, 10V, X5R, ±10%, SMD 0603; Manufacturer: Samsung Electro-Mechanics; Manufacturer Part Number: CL10A475KP8NNNL
footprint CAP-0603 (0603 (1608M) Capacitor)
pins: 1, 2

## CL10A475KQ8NNNC
designator C?  Capacitance: 4.7uF  (hidden comment: *)
Capacitor, Ceramic (MLCC), 4.7uF, ±10%, 6.3V, X5R, ±10%, SMD 0603; Manufacturer: Samsung Electro-Mechanics; Manufacturer Part Number: CL10A475KQ8NNNC
footprint CAP-0603 (0603 (1608M) Capacitor)
pins: 1, 2

## CL10A475MO8NNNC
designator C?  Capacitance: 4.7uF  (hidden comment: *)
Capacitor, Ceramic (MLCC), 4.7uF, ±20%, 16V, X5R, ±20%, SMD 0603; Manufacturer: Samsung Electro-Mechanics; Manufacturer Part Number: CL10A475MO8NNNC
footprint CAP-0603 (0603 (1608M) Capacitor)
pins: 1, 2

## CL10A475MP8NNNC
designator C?  Capacitance: 4.7uF  (hidden comment: *)
Capacitor, Ceramic (MLCC), 4.7uF, ±20%, 10V, X5R, ±20%, SMD 0603; Manufacturer: Samsung Electro-Mechanics; Manufacturer Part Number: CL10A475MP8NNNC
footprint CAP-0603 (0603 (1608M) Capacitor)
pins: 1, 2

## CL10A475MQ8NNNC
designator C?  Capacitance: 4.7uF  (hidden comment: *)
Capacitor, Ceramic (MLCC), 4.7uF, ±20%, 6.3V, X5R, ±20%, SMD 0603; Manufacturer: Samsung Electro-Mechanics; Manufacturer Part Number: CL10A475MQ8NNNC
footprint CAP-0603 (0603 (1608M) Capacitor)
pins: 1, 2

## CL10A476MQ8QRNC
designator C?  Capacitance: 47uF  (hidden comment: *)
Capacitor, Ceramic (MLCC), 47uF, ±20%, 6.3V, X5R, ±20%, SMD 0603; Manufacturer: Samsung Electro-Mechanics; Manufacturer Part Number: CL10A476MQ8QRNC
footprint CAP-0603 (0603 (1608M) Capacitor)
pins: 1, 2

## CL10A476MR8NRNE
designator C?  Capacitance: 47uF  (hidden comment: *)
Capacitor, Ceramic (MLCC), 47uF, ±20%, 4V, X5R, ±20%, SMD 0603; Manufacturer: Samsung Electro-Mechanics; Manufacturer Part Number: CL10A476MR8NRNE
footprint CAP-0603 (0603 (1608M) Capacitor)
pins: 1, 2

## CL10A476MR8NZNE
designator C?  Capacitance: 47uF  (hidden comment: *)
Capacitor, Ceramic (MLCC), 47uF, ±20%, 4V, X5R, ±20%, SMD 0603; Manufacturer: Samsung Electro-Mechanics; Manufacturer Part Number: CL10A476MR8NZNE
footprint CAP-0603 (0603 (1608M) Capacitor)
pins: 1, 2

## CL10B102JB8NFNC
designator C?  Capacitance: 1nF  (hidden comment: *)
Capacitor, Ceramic (MLCC), 1nF, ±5%, 50V, ±5%, SMD 0603; Manufacturer: Samsung Electro-Mechanics; Manufacturer Part Number: CL10B102JB8NFNC
footprint CAP-0603 (0603 (1608M) Capacitor)
pins: 1, 2

## CL10B102JB8NNNC
designator C?  Capacitance: 1nF  (hidden comment: *)
Capacitor, Ceramic (MLCC), 1nF, ±5%, 50V, X7R, ±5%, SMD 0603; Manufacturer: Samsung Electro-Mechanics; Manufacturer Part Number: CL10B102JB8NNNC
footprint CAP-0603 (0603 (1608M) Capacitor)
pins: 1, 2

## CL10B102KB8NFNC
designator C?  Capacitance: 1nF  (hidden comment: *)
Capacitor, Ceramic (MLCC), 1nF, ±10%, 50V, X7R, ±10%, SMD 0603; Manufacturer: Samsung Electro-Mechanics; Manufacturer Part Number: CL10B102KB8NFNC
footprint CAP-0603 (0603 (1608M) Capacitor)
pins: 1, 2

## CL10B102KB8WPNC
designator C?  Capacitance: 1nF  (hidden comment: *)
Capacitor, Ceramic (MLCC), 1nF, ±10%, 50V, X7R, ±10%, SMD 0603; Manufacturer: Samsung Electro-Mechanics; Manufacturer Part Number: CL10B102KB8WPNC
footprint CAP-0603 (0603 (1608M) Capacitor)
pins: 1, 2

## CL10B102KC8NNNC
designator C?  Capacitance: 1nF  (hidden comment: *)
Capacitor, Ceramic (MLCC), 1nF, ±10%, 100V, X7R, ±10%, SMD 0603; Manufacturer: Samsung Electro-Mechanics; Manufacturer Part Number: CL10B102KC8NNNC
footprint CAP-0603 (0603 (1608M) Capacitor)
pins: 1, 2

## CL10B102KC8WPNC
designator C?  Capacitance: 1nF  (hidden comment: *)
Capacitor, Ceramic (MLCC), 1nF, ±10%, 100V, X7R, ±10%, SMD 0603; Manufacturer: Samsung Electro-Mechanics; Manufacturer Part Number: CL10B102KC8WPNC
footprint CAP-0603 (0603 (1608M) Capacitor)
pins: 1, 2

## CL10B103JB8NNNC
designator C?  Capacitance: 10nF  (hidden comment: *)
Capacitor, Ceramic (MLCC), 10nF, ±5%, 50V, X7R, ±5%, SMD 0603; Manufacturer: Samsung Electro-Mechanics; Manufacturer Part Number: CL10B103JB8NNNC
footprint CAP-0603 (0603 (1608M) Capacitor)
pins: 1, 2

## CL10B103KA8WPNC
designator C?  Capacitance: 10nF  (hidden comment: *)
Capacitor, Ceramic (MLCC), 10nF, ±10%, 25V, X7R, ±10%, SMD 0603; Manufacturer: Samsung Electro-Mechanics; Manufacturer Part Number: CL10B103KA8WPNC
footprint CAP-0603 (0603 (1608M) Capacitor)
pins: 1, 2

## CL10B103KB8NNNC
designator C?  Capacitance: 10nF  (hidden comment: *)
Capacitor, Ceramic (MLCC), 10nF, ±10%, 50V, X7R, ±10%, SMD 0603; Manufacturer: Samsung Electro-Mechanics; Manufacturer Part Number: CL10B103KB8NNNC
footprint CAP-0603 (0603 (1608M) Capacitor)
pins: 1, 2

## CL10B103KB8WPJC
designator C?  Capacitance: 10nF  (hidden comment: *)
Capacitor, Ceramic (MLCC), 10nF, ±10%, 50V, ±10%, SMD 0603; Manufacturer: Samsung Electro-Mechanics; Manufacturer Part Number: CL10B103KB8WPJC
footprint CAP-0603 (0603 (1608M) Capacitor)
pins: 1, 2

## CL10B103KB8WPNC
designator C?  Capacitance: 10nF  (hidden comment: *)
Capacitor, Ceramic (MLCC), 10nF, ±10%, 50V, X7R, ±10%, SMD 0603; Manufacturer: Samsung Electro-Mechanics; Manufacturer Part Number: CL10B103KB8WPNC
footprint CAP-0603 (0603 (1608M) Capacitor)
pins: 1, 2

## CL10B103KB85PNC
designator C?  Capacitance: 10nF  (hidden comment: *)
Capacitor, Ceramic (MLCC), 10nF, ±10%, 50V, X7R, ±10%, SMD 0603; Manufacturer: Samsung Electro-Mechanics; Manufacturer Part Number: CL10B103KB85PNC
footprint CAP-0603 (0603 (1608M) Capacitor)
pins: 1, 2

## CL10B103KC8NNNC
designator C?  Capacitance: 10nF  (hidden comment: *)
Capacitor, Ceramic (MLCC), 10nF, ±10%, 100V, X7R, ±10%, SMD 0603; Manufacturer: Samsung Electro-Mechanics; Manufacturer Part Number: CL10B103KC8NNNC
footprint CAP-0603 (0603 (1608M) Capacitor)
pins: 1, 2

## CL10B103KC8WPNC
designator C?  Capacitance: 10nF  (hidden comment: *)
Capacitor, Ceramic (MLCC), 10nF, ±10%, 100V, X7R, ±10%, SMD 0603; Manufacturer: Samsung Electro-Mechanics; Manufacturer Part Number: CL10B103KC8WPNC
footprint CAP-0603 (0603 (1608M) Capacitor)
pins: 1, 2

## CL10B104JB8NNNC
designator C?  Capacitance: 100nF  (hidden comment: *)
Capacitor, Ceramic (MLCC), 100nF, ±5%, 50V, X7R, ±5%, SMD 0603; Manufacturer: Samsung Electro-Mechanics; Manufacturer Part Number: CL10B104JB8NNNC
footprint CAP-0603 (0603 (1608M) Capacitor)
pins: 1, 2

## CL10B104KA8NNNC
designator C?  Capacitance: 100nF  (hidden comment: *)
Capacitor, Ceramic (MLCC), 100nF, ±10%, 25V, X7R, ±10%, SMD 0603; Manufacturer: Samsung Electro-Mechanics; Manufacturer Part Number: CL10B104KA8NNNC
footprint CAP-0603 (0603 (1608M) Capacitor)
pins: 1, 2

## CL10B104KB8NFNC
designator C?  Capacitance: 100nF  (hidden comment: *)
Capacitor, Ceramic (MLCC), 100nF, ±10%, 50V, X7R, ±10%, SMD 0603; Manufacturer: Samsung Electro-Mechanics; Manufacturer Part Number: CL10B104KB8NFNC
footprint CAP-0603 (0603 (1608M) Capacitor)
pins: 1, 2

## CL10B104KB8NNNC
designator C?  Capacitance: 100nF  (hidden comment: *)
Capacitor, Ceramic (MLCC), 100nF, ±10%, 50V, X7R, ±10%, SMD 0603; Manufacturer: Samsung Electro-Mechanics; Manufacturer Part Number: CL10B104KB8NNNC
footprint CAP-0603 (0603 (1608M) Capacitor)
pins: 1, 2

## CL10B104KB8NNNL
designator C?  Capacitance: 100nF  (hidden comment: *)
Capacitor, Ceramic (MLCC), 100nF, ±10%, 50V, ±10%, SMD 0603; Manufacturer: Samsung Electro-Mechanics; Manufacturer Part Number: CL10B104KB8NNNL
footprint CAP-0603 (0603 (1608M) Capacitor)
pins: 1, 2

## CL10B104KB8VPJC
designator C?  Capacitance: 100nF  (hidden comment: *)
Capacitor, Ceramic (MLCC), 100nF, ±10%, 50V, ±10%, SMD 0603; Manufacturer: Samsung Electro-Mechanics; Manufacturer Part Number: CL10B104KB8VPJC
footprint CAP-0603 (0603 (1608M) Capacitor)
pins: 1, 2

## CL10B104KB8WPNC
designator C?  Capacitance: 100nF  (hidden comment: *)
Capacitor, Ceramic (MLCC), 100nF, ±10%, 50V, X7R, ±10%, SMD 0603; Manufacturer: Samsung Electro-Mechanics; Manufacturer Part Number: CL10B104KB8WPNC
footprint CAP-0603 (0603 (1608M) Capacitor)
pins: 1, 2

## CL10B104KC8NNNC
designator C?  Capacitance: 100nF  (hidden comment: *)
Capacitor, Ceramic (MLCC), 100nF, ±10%, 100V, X7R, ±10%, SMD 0603; Manufacturer: Samsung Electro-Mechanics; Manufacturer Part Number: CL10B104KC8NNNC
footprint CAP-0603 (0603 (1608M) Capacitor)
pins: 1, 2

## CL10B104KC8VPNC
designator C?  Capacitance: 100nF  (hidden comment: *)
Capacitor, Ceramic (MLCC), 100nF, ±10%, 100V, X7R, ±10%, SMD 0603; Manufacturer: Samsung Electro-Mechanics; Manufacturer Part Number: CL10B104KC8VPNC
footprint CAP-0603 (0603 (1608M) Capacitor)
pins: 1, 2

## CL10B104KO8NFNC
designator C?  Capacitance: 100nF  (hidden comment: *)
Capacitor, Ceramic (MLCC), 100nF, ±10%, 16V, X7R, ±10%, SMD 0603; Manufacturer: Samsung Electro-Mechanics; Manufacturer Part Number: CL10B104KO8NFNC
footprint CAP-0603 (0603 (1608M) Capacitor)
pins: 1, 2

## CL10B104KO8NNNC
designator C?  Capacitance: 100nF  (hidden comment: *)
Capacitor, Ceramic (MLCC), 100nF, ±10%, 16V, X7R, ±10%, SMD 0603; Manufacturer: Samsung Electro-Mechanics; Manufacturer Part Number: CL10B104KO8NNNC
footprint CAP-0603 (0603 (1608M) Capacitor)
pins: 1, 2

## CL10B105KA8NFNC
designator C?  Capacitance: 1uF  (hidden comment: *)
Capacitor, Ceramic (MLCC), 1uF, ±10%, 25V, X7R, ±10%, SMD 0603; Manufacturer: Samsung Electro-Mechanics; Manufacturer Part Number: CL10B105KA8NFNC
footprint CAP-0603 (0603 (1608M) Capacitor)
pins: 1, 2

## CL10B105KA8NNNC
designator C?  Capacitance: 1uF  (hidden comment: *)
Capacitor, Ceramic (MLCC), 1uF, ±10%, 25V, X7R, ±10%, SMD 0603; Manufacturer: Samsung Electro-Mechanics; Manufacturer Part Number: CL10B105KA8NNNC
footprint CAP-0603 (0603 (1608M) Capacitor)
pins: 1, 2

## CL10B105KA8NNWC
designator C?  Capacitance: 1uF  (hidden comment: *)
Capacitor, Ceramic (MLCC), 1uF, ±10%, 25V, X7R, ±10%, SMD 0603; Manufacturer: Samsung Electro-Mechanics; Manufacturer Part Number: CL10B105KA8NNWC
footprint CAP-0603 (0603 (1608M) Capacitor)
pins: 1, 2

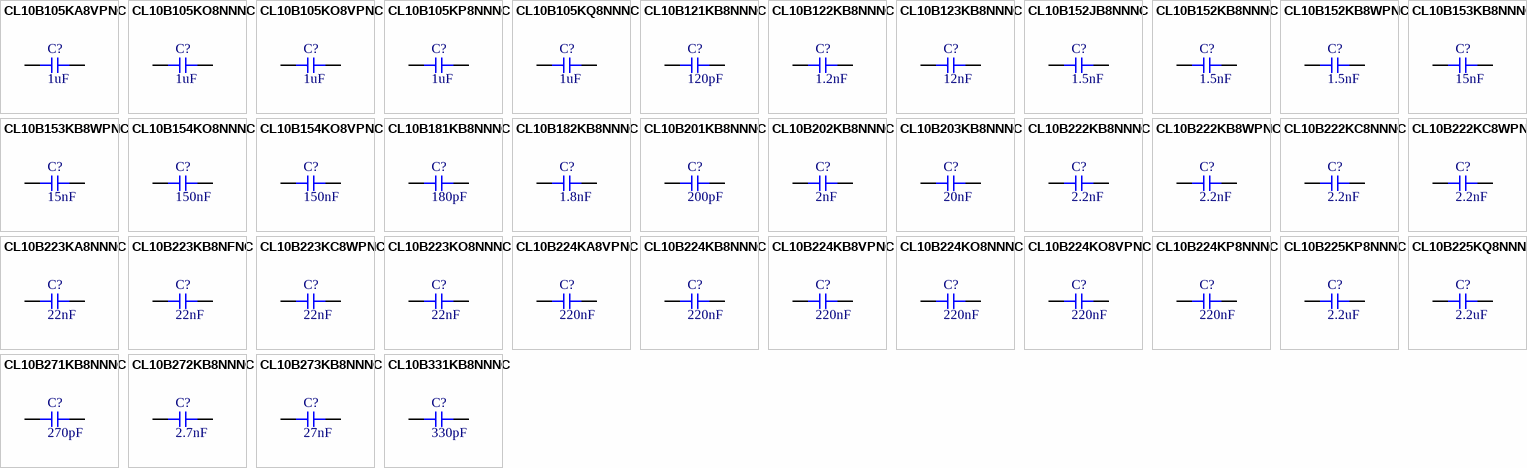
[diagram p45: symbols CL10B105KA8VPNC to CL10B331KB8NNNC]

## CL10B105KA8VPNC
designator C?  Capacitance: 1uF  (hidden comment: *)
Capacitor, Ceramic (MLCC), 1uF, ±10%, 25V, X7R, ±10%, SMD 0603; Manufacturer: Samsung Electro-Mechanics; Manufacturer Part Number: CL10B105KA8VPNC
footprint CAP-0603 (0603 (1608M) Capacitor)
pins: 1, 2

## CL10B105KO8NNNC
designator C?  Capacitance: 1uF  (hidden comment: *)
Capacitor, Ceramic (MLCC), 1uF, ±10%, 16V, X7R, ±10%, SMD 0603; Manufacturer: Samsung Electro-Mechanics; Manufacturer Part Number: CL10B105KO8NNNC
footprint CAP-0603 (0603 (1608M) Capacitor)
pins: 1, 2

## CL10B105KO8VPNC
designator C?  Capacitance: 1uF  (hidden comment: *)
Capacitor, Ceramic (MLCC), 1uF, ±10%, 16V, X7R, ±10%, SMD 0603; Manufacturer: Samsung Electro-Mechanics; Manufacturer Part Number: CL10B105KO8VPNC
footprint CAP-0603 (0603 (1608M) Capacitor)
pins: 1, 2

## CL10B105KP8NNNC
designator C?  Capacitance: 1uF  (hidden comment: *)
Capacitor, Ceramic (MLCC), 1uF, ±10%, 10V, X7R, ±10%, SMD 0603; Manufacturer: Samsung Electro-Mechanics; Manufacturer Part Number: CL10B105KP8NNNC
footprint CAP-0603 (0603 (1608M) Capacitor)
pins: 1, 2

## CL10B105KQ8NNNC
designator C?  Capacitance: 1uF  (hidden comment: *)
Capacitor, Ceramic (MLCC), 1uF, ±10%, 6.3V, X7R, ±10%, SMD 0603; Manufacturer: Samsung Electro-Mechanics; Manufacturer Part Number: CL10B105KQ8NNNC
footprint CAP-0603 (0603 (1608M) Capacitor)
pins: 1, 2

## CL10B121KB8NNNC
designator C?  Capacitance: 120pF  (hidden comment: *)
Capacitor, Ceramic (MLCC), 120pF, ±10%, 50V, X7R, ±10%, SMD 0603; Manufacturer: Samsung Electro-Mechanics; Manufacturer Part Number: CL10B121KB8NNNC
footprint CAP-0603 (0603 (1608M) Capacitor)
pins: 1, 2

## CL10B122KB8NNNC
designator C?  Capacitance: 1.2nF  (hidden comment: *)
Capacitor, Ceramic (MLCC), 1.2nF, ±10%, 50V, X7R, ±10%, SMD 0603; Manufacturer: Samsung Electro-Mechanics; Manufacturer Part Number: CL10B122KB8NNNC
footprint CAP-0603 (0603 (1608M) Capacitor)
pins: 1, 2

## CL10B123KB8NNNC
designator C?  Capacitance: 12nF  (hidden comment: *)
Capacitor, Ceramic (MLCC), 12nF, ±10%, 50V, X7R, ±10%, SMD 0603; Manufacturer: Samsung Electro-Mechanics; Manufacturer Part Number: CL10B123KB8NNNC
footprint CAP-0603 (0603 (1608M) Capacitor)
pins: 1, 2

## CL10B152JB8NNNC
designator C?  Capacitance: 1.5nF  (hidden comment: *)
Capacitor, Ceramic (MLCC), 1.5nF, ±5%, 50V, X7R, ±5%, SMD 0603; Manufacturer: Samsung Electro-Mechanics; Manufacturer Part Number: CL10B152JB8NNNC
footprint CAP-0603 (0603 (1608M) Capacitor)
pins: 1, 2

## CL10B152KB8NNNC
designator C?  Capacitance: 1.5nF  (hidden comment: *)
Capacitor, Ceramic (MLCC), 1.5nF, ±10%, 50V, X7R, ±10%, SMD 0603; Manufacturer: Samsung Electro-Mechanics; Manufacturer Part Number: CL10B152KB8NNNC
footprint CAP-0603 (0603 (1608M) Capacitor)
pins: 1, 2

## CL10B152KB8WPNC
designator C?  Capacitance: 1.5nF  (hidden comment: *)
Capacitor, Ceramic (MLCC), 1.5nF, ±10%, 50V, X7R, ±10%, SMD 0603; Manufacturer: Samsung Electro-Mechanics; Manufacturer Part Number: CL10B152KB8WPNC
footprint CAP-0603 (0603 (1608M) Capacitor)
pins: 1, 2

## CL10B153KB8NNNC
designator C?  Capacitance: 15nF  (hidden comment: *)
Capacitor, Ceramic (MLCC), 15nF, ±10%, 50V, X7R, ±10%, SMD 0603; Manufacturer: Samsung Electro-Mechanics; Manufacturer Part Number: CL10B153KB8NNNC
footprint CAP-0603 (0603 (1608M) Capacitor)
pins: 1, 2

## CL10B153KB8WPNC
designator C?  Capacitance: 15nF  (hidden comment: *)
Capacitor, Ceramic (MLCC), 15nF, ±10%, 50V, X7R, ±10%, SMD 0603; Manufacturer: Samsung Electro-Mechanics; Manufacturer Part Number: CL10B153KB8WPNC
footprint CAP-0603 (0603 (1608M) Capacitor)
pins: 1, 2

## CL10B154KO8NNNC
designator C?  Capacitance: 150nF  (hidden comment: *)
Capacitor, Ceramic (MLCC), 150nF, ±10%, 16V, X7R, ±10%, SMD 0603; Manufacturer: Samsung Electro-Mechanics; Manufacturer Part Number: CL10B154KO8NNNC
footprint CAP-0603 (0603 (1608M) Capacitor)
pins: 1, 2

## CL10B154KO8VPNC
designator C?  Capacitance: 150nF  (hidden comment: *)
Capacitor, Ceramic (MLCC), 150nF, ±10%, 16V, X7R, ±10%, SMD 0603; Manufacturer: Samsung Electro-Mechanics; Manufacturer Part Number: CL10B154KO8VPNC
footprint CAP-0603 (0603 (1608M) Capacitor)
pins: 1, 2

## CL10B181KB8NNNC
designator C?  Capacitance: 180pF  (hidden comment: *)
Capacitor, Ceramic (MLCC), 180pF, ±10%, 50V, X7R, ±10%, SMD 0603; Manufacturer: Samsung Electro-Mechanics; Manufacturer Part Number: CL10B181KB8NNNC
footprint CAP-0603 (0603 (1608M) Capacitor)
pins: 1, 2

## CL10B182KB8NNNC
designator C?  Capacitance: 1.8nF  (hidden comment: *)
Capacitor, Ceramic (MLCC), 1.8nF, ±10%, 50V, X7R, ±10%, SMD 0603; Manufacturer: Samsung Electro-Mechanics; Manufacturer Part Number: CL10B182KB8NNNC
footprint CAP-0603 (0603 (1608M) Capacitor)
pins: 1, 2

## CL10B201KB8NNNC
designator C?  Capacitance: 200pF  (hidden comment: *)
Capacitor, Ceramic (MLCC), 200pF, ±10%, 50V, X7R, ±10%, SMD 0603; Manufacturer: Samsung Electro-Mechanics; Manufacturer Part Number: CL10B201KB8NNNC
footprint CAP-0603 (0603 (1608M) Capacitor)
pins: 1, 2

## CL10B202KB8NNNC
designator C?  Capacitance: 2nF  (hidden comment: *)
Capacitor, Ceramic (MLCC), 2nF, ±10%, 50V, X7R, ±10%, SMD 0603; Manufacturer: Samsung Electro-Mechanics; Manufacturer Part Number: CL10B202KB8NNNC
footprint CAP-0603 (0603 (1608M) Capacitor)
pins: 1, 2

## CL10B203KB8NNNC
designator C?  Capacitance: 20nF  (hidden comment: *)
Capacitor, Ceramic (MLCC), 20nF, ±10%, 50V, X7R, ±10%, SMD 0603; Manufacturer: Samsung Electro-Mechanics; Manufacturer Part Number: CL10B203KB8NNNC
footprint CAP-0603 (0603 (1608M) Capacitor)
pins: 1, 2

## CL10B222KB8NNNC
designator C?  Capacitance: 2.2nF  (hidden comment: *)
Capacitor, Ceramic (MLCC), 2.2nF, ±10%, 50V, X7R, ±10%, SMD 0603; Manufacturer: Samsung Electro-Mechanics; Manufacturer Part Number: CL10B222KB8NNNC
footprint CAP-0603 (0603 (1608M) Capacitor)
pins: 1, 2

## CL10B222KB8WPNC
designator C?  Capacitance: 2.2nF  (hidden comment: *)
Capacitor, Ceramic (MLCC), 2.2nF, ±10%, 50V, X7R, ±10%, SMD 0603; Manufacturer: Samsung Electro-Mechanics; Manufacturer Part Number: CL10B222KB8WPNC
footprint CAP-0603 (0603 (1608M) Capacitor)
pins: 1, 2

## CL10B222KC8NNNC
designator C?  Capacitance: 2.2nF  (hidden comment: *)
Capacitor, Ceramic (MLCC), 2.2nF, ±10%, 100V, X7R, ±10%, SMD 0603; Manufacturer: Samsung Electro-Mechanics; Manufacturer Part Number: CL10B222KC8NNNC
footprint CAP-0603 (0603 (1608M) Capacitor)
pins: 1, 2

## CL10B222KC8WPNC
designator C?  Capacitance: 2.2nF  (hidden comment: *)
Capacitor, Ceramic (MLCC), 2.2nF, ±10%, 100V, X7R, ±10%, SMD 0603; Manufacturer: Samsung Electro-Mechanics; Manufacturer Part Number: CL10B222KC8WPNC
footprint CAP-0603 (0603 (1608M) Capacitor)
pins: 1, 2

## CL10B223KA8NNNC
designator C?  Capacitance: 22nF  (hidden comment: *)
Capacitor, Ceramic (MLCC), 22nF, ±10%, 25V, X7R, ±10%, SMD 0603; Manufacturer: Samsung Electro-Mechanics; Manufacturer Part Number: CL10B223KA8NNNC
footprint CAP-0603 (0603 (1608M) Capacitor)
pins: 1, 2

## CL10B223KB8NFNC
designator C?  Capacitance: 22nF  (hidden comment: *)
Capacitor, Ceramic (MLCC), 22nF, ±10%, 50V, X7R, ±10%, SMD 0603; Manufacturer: Samsung Electro-Mechanics; Manufacturer Part Number: CL10B223KB8NFNC
footprint CAP-0603 (0603 (1608M) Capacitor)
pins: 1, 2

## CL10B223KC8WPNC
designator C?  Capacitance: 22nF  (hidden comment: *)
Capacitor, Ceramic (MLCC), 22nF, ±10%, 100V, X7R, ±10%, SMD 0603; Manufacturer: Samsung Electro-Mechanics; Manufacturer Part Number: CL10B223KC8WPNC
footprint CAP-0603 (0603 (1608M) Capacitor)
pins: 1, 2

## CL10B223KO8NNNC
designator C?  Capacitance: 22nF  (hidden comment: *)
Capacitor, Ceramic (MLCC), 22nF, ±10%, 16V, X7R, ±10%, SMD 0603; Manufacturer: Samsung Electro-Mechanics; Manufacturer Part Number: CL10B223KO8NNNC
footprint CAP-0603 (0603 (1608M) Capacitor)
pins: 1, 2

## CL10B224KA8VPNC
designator C?  Capacitance: 220nF  (hidden comment: *)
Capacitor, Ceramic (MLCC), 220nF, ±10%, 25V, X7R, ±10%, SMD 0603; Manufacturer: Samsung Electro-Mechanics; Manufacturer Part Number: CL10B224KA8VPNC
footprint CAP-0603 (0603 (1608M) Capacitor)
pins: 1, 2

## CL10B224KB8NNNC
designator C?  Capacitance: 220nF  (hidden comment: *)
Capacitor, Ceramic (MLCC), 220nF, ±10%, 50V, X7R, ±10%, SMD 0603; Manufacturer: Samsung Electro-Mechanics; Manufacturer Part Number: CL10B224KB8NNNC
footprint CAP-0603 (0603 (1608M) Capacitor)
pins: 1, 2

## CL10B224KB8VPNC
designator C?  Capacitance: 220nF  (hidden comment: *)
Capacitor, Ceramic (MLCC), 220nF, ±10%, 50V, X7R, ±10%, SMD 0603; Manufacturer: Samsung Electro-Mechanics; Manufacturer Part Number: CL10B224KB8VPNC
footprint CAP-0603 (0603 (1608M) Capacitor)
pins: 1, 2

## CL10B224KO8NNNC
designator C?  Capacitance: 220nF  (hidden comment: *)
Capacitor, Ceramic (MLCC), 220nF, ±10%, 16V, X7R, ±10%, SMD 0603; Manufacturer: Samsung Electro-Mechanics; Manufacturer Part Number: CL10B224KO8NNNC
footprint CAP-0603 (0603 (1608M) Capacitor)
pins: 1, 2

## CL10B224KO8VPNC
designator C?  Capacitance: 220nF  (hidden comment: *)
Capacitor, Ceramic (MLCC), 220nF, ±10%, 16V, X7R, ±10%, SMD 0603; Manufacturer: Samsung Electro-Mechanics; Manufacturer Part Number: CL10B224KO8VPNC
footprint CAP-0603 (0603 (1608M) Capacitor)
pins: 1, 2

## CL10B224KP8NNNC
designator C?  Capacitance: 220nF  (hidden comment: *)
Capacitor, Ceramic (MLCC), 220nF, ±10%, 10V, X7R, ±10%, SMD 0603; Manufacturer: Samsung Electro-Mechanics; Manufacturer Part Number: CL10B224KP8NNNC
footprint CAP-0603 (0603 (1608M) Capacitor)
pins: 1, 2

## CL10B225KP8NNNC
designator C?  Capacitance: 2.2uF  (hidden comment: *)
Capacitor, Ceramic (MLCC), 2.2uF, ±10%, 10V, X7R, ±10%, SMD 0603; Manufacturer: Samsung Electro-Mechanics; Manufacturer Part Number: CL10B225KP8NNNC
footprint CAP-0603 (0603 (1608M) Capacitor)
pins: 1, 2

## CL10B225KQ8NNNC
designator C?  Capacitance: 2.2uF  (hidden comment: *)
Capacitor, Ceramic (MLCC), 2.2uF, ±10%, 6.3V, X7R, ±10%, SMD 0603; Manufacturer: Samsung Electro-Mechanics; Manufacturer Part Number: CL10B225KQ8NNNC
footprint CAP-0603 (0603 (1608M) Capacitor)
pins: 1, 2

## CL10B271KB8NNNC
designator C?  Capacitance: 270pF  (hidden comment: *)
Capacitor, Ceramic (MLCC), 270pF, ±10%, 50V, X7R, ±10%, SMD 0603; Manufacturer: Samsung Electro-Mechanics; Manufacturer Part Number: CL10B271KB8NNNC
footprint CAP-0603 (0603 (1608M) Capacitor)
pins: 1, 2

## CL10B272KB8NNNC
designator C?  Capacitance: 2.7nF  (hidden comment: *)
Capacitor, Ceramic (MLCC), 2.7nF, ±10%, 50V, X7R, ±10%, SMD 0603; Manufacturer: Samsung Electro-Mechanics; Manufacturer Part Number: CL10B272KB8NNNC
footprint CAP-0603 (0603 (1608M) Capacitor)
pins: 1, 2

## CL10B273KB8NNNC
designator C?  Capacitance: 27nF  (hidden comment: *)
Capacitor, Ceramic (MLCC), 27nF, ±10%, 50V, X7R, ±10%, SMD 0603; Manufacturer: Samsung Electro-Mechanics; Manufacturer Part Number: CL10B273KB8NNNC
footprint CAP-0603 (0603 (1608M) Capacitor)
pins: 1, 2

## CL10B331KB8NNNC
designator C?  Capacitance: 330pF  (hidden comment: *)
Capacitor, Ceramic (MLCC), 330pF, ±10%, 50V, X7R, ±10%, SMD 0603; Manufacturer: Samsung Electro-Mechanics; Manufacturer Part Number: CL10B331KB8NNNC
footprint CAP-0603 (0603 (1608M) Capacitor)
pins: 1, 2

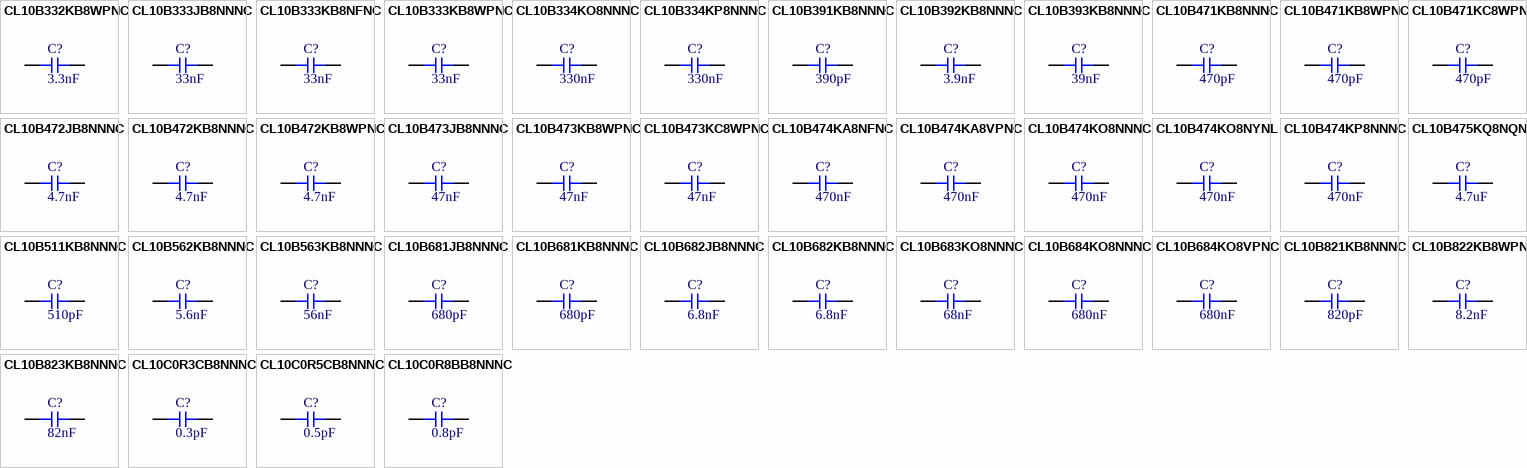
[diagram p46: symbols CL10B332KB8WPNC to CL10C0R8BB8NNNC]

## CL10B332KB8WPNC
designator C?  Capacitance: 3.3nF  (hidden comment: *)
Capacitor, Ceramic (MLCC), 3.3nF, ±10%, 50V, X7R, ±10%, SMD 0603; Manufacturer: Samsung Electro-Mechanics; Manufacturer Part Number: CL10B332KB8WPNC
footprint CAP-0603 (0603 (1608M) Capacitor)
pins: 1, 2

## CL10B333JB8NNNC
designator C?  Capacitance: 33nF  (hidden comment: *)
Capacitor, Ceramic (MLCC), 33nF, ±5%, 50V, X7R, ±5%, SMD 0603; Manufacturer: Samsung Electro-Mechanics; Manufacturer Part Number: CL10B333JB8NNNC
footprint CAP-0603 (0603 (1608M) Capacitor)
pins: 1, 2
